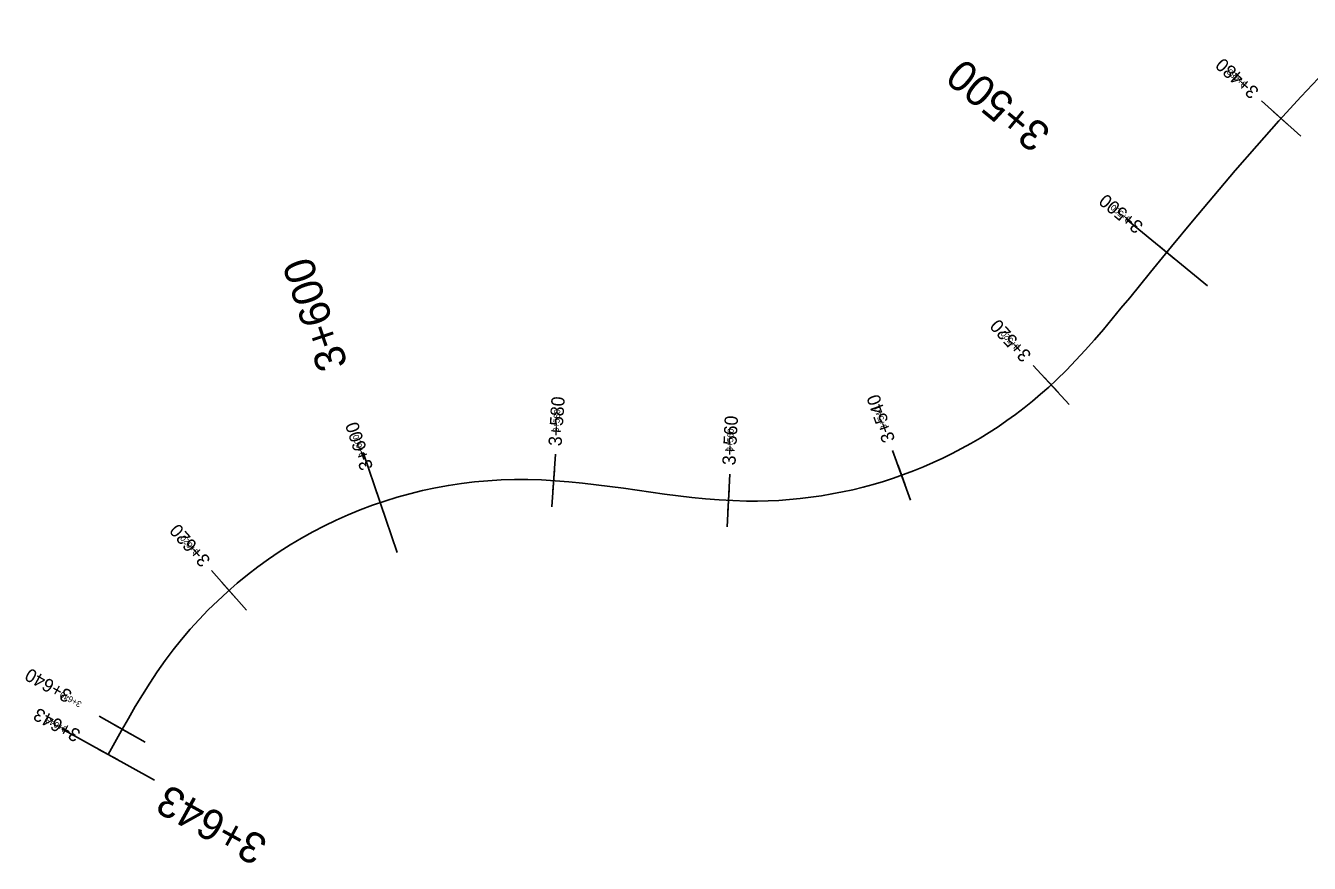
# Model space of a CAD drawing. Extents: x 0 to 511895, y 0 to 6211943.
# Drawn here: x 511370.8 to 511516.6, y 6211417.1 to 6211512.3 of the extents above; entities that cross this region are included whole.
import ezdxf

# ---------------------------------------------------------------- set-up
doc = ezdxf.new("R2010")
doc.units = 0
for name, color, linetype in [('TV_L_---_CL---_C', 7, 'Continuous'), ('TV_L_---_CL---_TC', 7, 'Continuous'), ('TV_L_HOR_Statn_T_00200', 7, 'Continuous'), ('TV_L_HOR_Statn_T_00500', 7, 'Continuous'), ('TV_L_HOR_Statn_T_01000', 7, 'Continuous'), ('TV_L_HOR_Statn_Tic_00200', 7, 'Continuous'), ('TV_L_HOR_Statn_Tic_00500', 7, 'Continuous'), ('TV_L_HOR_Statn_Tic_01000', 7, 'Continuous')]:
    doc.layers.add(name, color=color, linetype=linetype)

msp = doc.modelspace()

# ---------------------------------------------------------------- linework, layer by layer
at = {"layer": 'TV_L_---_CL---_C'}
for centre, start, end in [((511453.44, 6211508.24), 269.135, 313.5845), ((511427.07, 6211410.7), 89.135, 143.9525)]:
    msp.add_arc(centre, 50, start, end, dxfattribs=at)
at = {"layer": 'TV_L_---_CL---_TC'}
for points in [[(511523.56, 6211512.25), (511520.88, 6211509.62), (511518.26, 6211506.93), (511515.69, 6211504.2), (511513.16, 6211501.43), (511510.66, 6211498.62), (511508.2, 6211495.79), (511505.77, 6211492.93), (511503.36, 6211490.05), (511500.97, 6211487.16), (511498.59, 6211484.26), (511496.21, 6211481.35)], [(511496.21, 6211481.35), (511495.22, 6211480.14), (511494.23, 6211478.94), (511493.23, 6211477.74), (511492.21, 6211476.56), (511491.17, 6211475.39), (511490.11, 6211474.24), (511489.03, 6211473.11), (511487.91, 6211472.02)], [(511440.26, 6211459.47), (511438.71, 6211459.69), (511437.16, 6211459.9), (511435.61, 6211460.1), (511434.06, 6211460.28), (511432.5, 6211460.43), (511430.95, 6211460.56), (511429.39, 6211460.65), (511427.82, 6211460.7)], [(511452.69, 6211458.24), (511451.12, 6211458.29), (511449.56, 6211458.38), (511448.01, 6211458.5), (511446.45, 6211458.66), (511444.9, 6211458.84), (511443.35, 6211459.04), (511441.8, 6211459.25), (511440.26, 6211459.47)], [(511386.64, 6211440.13), (511385.74, 6211438.85), (511384.88, 6211437.55), (511384.04, 6211436.23), (511383.23, 6211434.89), (511382.45, 6211433.54), (511381.68, 6211432.18), (511380.91, 6211430.82), (511380.16, 6211429.45)]]:
    msp.add_lwpolyline(points, dxfattribs=at)
at = {"layer": 'TV_L_HOR_Statn_Tic_00200'}
for points in [[(511514.3, 6211500.91), (511512.52, 6211502.52)], [(511501.35, 6211485.74), (511499.5, 6211487.26)], [(511488.11, 6211470.56), (511486.48, 6211472.32)], [(511470.7, 6211460.03), (511469.89, 6211462.29)], [(511430.68, 6211459.38), (511430.85, 6211461.77)], [(511411.44, 6211456.93), (511410.67, 6211459.21)], [(511450.57, 6211457.11), (511450.69, 6211459.51)], [(511394.67, 6211447.2), (511393.08, 6211448.99)], [(511382.8, 6211431.73), (511380.71, 6211432.91)], [(511381.21, 6211428.87), (511379.11, 6211430.03)], [(511381.21, 6211428.87), (511379.11, 6211430.03)]]:
    msp.add_lwpolyline(points, dxfattribs=at)
at = {"layer": 'TV_L_HOR_Statn_Tic_00500'}
for points in [[(511514.3, 6211500.91), (511512.52, 6211502.52)], [(511501.35, 6211485.74), (511499.5, 6211487.26)], [(511488.11, 6211470.56), (511486.48, 6211472.32)], [(511470.7, 6211460.03), (511469.89, 6211462.29)], [(511430.68, 6211459.38), (511430.85, 6211461.77)], [(511411.44, 6211456.93), (511410.67, 6211459.21)], [(511450.57, 6211457.11), (511450.69, 6211459.51)], [(511394.67, 6211447.2), (511393.08, 6211448.99)], [(511382.8, 6211431.73), (511380.71, 6211432.91)], [(511381.21, 6211428.87), (511379.11, 6211430.03)], [(511381.21, 6211428.87), (511379.11, 6211430.03)]]:
    msp.add_lwpolyline(points, dxfattribs=at)
at = {"layer": 'TV_L_HOR_Statn_Tic_01000'}
for points in [[(511515.64, 6211499.7), (511511.18, 6211503.72)], [(511505.06, 6211482.69), (511495.79, 6211490.31)], [(511489.33, 6211469.23), (511485.26, 6211473.65)], [(511412.98, 6211452.39), (511409.13, 6211463.75)], [(511430.56, 6211457.58), (511430.97, 6211463.57)], [(511471.3, 6211458.34), (511469.28, 6211463.99)], [(511450.47, 6211455.32), (511450.79, 6211461.31)], [(511395.87, 6211445.85), (511391.88, 6211450.34)], [(511384.37, 6211430.85), (511379.14, 6211433.79)], [(511385.41, 6211426.55), (511374.91, 6211432.35)], [(511385.41, 6211426.55), (511374.91, 6211432.35)]]:
    msp.add_lwpolyline(points, dxfattribs=at)

# ---------------------------------------------------------------- texts
at = {"layer": 'TV_L_HOR_Statn_T_00200'}
for s, rotation, p in [('3+480', 137.9296, (511509.59, 6211505.66)), ('3+500', 140.571, (511496.42, 6211490.34)), ('3+520', 132.6148, (511483.79, 6211475.75)), ('3+580', 86.1593, (511431.36, 6211466.02)), ('3+540', 109.6965, (511468.69, 6211466.52)), ('3+560', 86.972, (511451.1, 6211463.84)), ('3+600', 108.6805, (511409.4, 6211463.38)), ('3+620', 131.5988, (511390.54, 6211452.47)), ('3+640', 150.6212, (511377.21, 6211435.37)), ('3+643', 151.1145, (511375.6, 6211432.48))]:
    msp.add_text(s, height=0.7, rotation=rotation, dxfattribs=at).set_placement(p)
at = {"layer": 'TV_L_HOR_Statn_T_00500'}
for s, rotation, p in [('3+480', 137.9296, (511511, 6211504.92)), ('3+500', 140.571, (511497.87, 6211489.67)), ('3+520', 132.6148, (511485.13, 6211474.89)), ('3+580', 86.1593, (511431.66, 6211464.45)), ('3+540', 109.6965, (511469.59, 6211465.2)), ('3+560', 86.972, (511451.42, 6211462.28)), ('3+600', 108.6805, (511410.28, 6211462.04)), ('3+620', 131.5988, (511391.87, 6211451.58)), ('3+640', 150.6212, (511376.18, 6211436.56)), ('3+643', 151.1145, (511377.15, 6211432.09))]:
    msp.add_text(s, height=1.5, rotation=rotation, dxfattribs=at).set_placement(p)
at = {"layer": 'TV_L_HOR_Statn_T_01000'}
for s, rotation, p in [('3+500', 140.571, (511487.45, 6211500.35)), ('3+600', 108.6805, (511407.42, 6211473.74)), ('3+643', 151.1145, (511398.49, 6211419.79))]:
    msp.add_text(s, height=3.5, rotation=rotation, dxfattribs=at).set_placement(p)

doc.saveas('drawing.dxf')
